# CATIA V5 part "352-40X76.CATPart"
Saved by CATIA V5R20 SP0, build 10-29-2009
Part number: 352-40X76
Definition: NONE
Nomenclature: 352-40X76
Source: Unknown
Description: 352-40X76
Bounding box of the stored display mesh (mm): x 0 to 76, y -24 to 24, z -24 to 24
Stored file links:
  C:\Users\Utente\Desktop\IO LAVORO\3D X SITO CF\X SITO\PLASTICA\352\352-40X76.CATPart

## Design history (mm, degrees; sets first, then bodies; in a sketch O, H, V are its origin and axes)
Body1 "352-40X76" (main body)
  Solid1: solid without history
